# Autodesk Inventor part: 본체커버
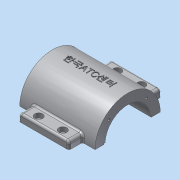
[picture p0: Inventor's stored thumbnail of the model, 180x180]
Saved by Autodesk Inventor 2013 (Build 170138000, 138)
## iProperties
Created: 2015-12
Part Number: 본체커버
Material: 알루미늄 6061
Document SubType Name: Modeling
Designer: mduedu
Density: 2.71 g/cm^3
Mass: 199.348 g
Surface Area: 200.806 cm^2
Volume: 73.5601 cm^3
Author: mduedu
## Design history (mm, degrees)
sketch "스케치1"
  geometry: L1 (45, 40)-(-45, 40); L2 (-45, 40)-(-45, -40); L3 (-45, -40)-(45, -40); L4 (45, -40)-(45, 40); L5 (45, 40)-(-45, -40); L6 (-45, 40)-(45, -40); 1 further point
  constraints: 12 end point, 2 midpoint, 2 parallel, 1 horizontal, 1 perpendicular
  dimensions: "d0" = 90 distance of L2.end L3.end; "d2" = 80 distance of L1.end L2.end
extrude "돌출1" new body sketch "스케치1" distance "d3" = 10; taper "d4" = 0 deg
sketch "스케치2"
  geometry: L1 (0, 40)-(0, -40) reference; C1 r 32.5 at (80, 0); 1 further point
  constraints: 1 centre point
  dimensions: "d5" = 65 diameter of C1; "d6" = 80 distance from line of C1.centre L1
extrude "돌출2" join sketch "스케치2" stored distance "d7" = 75; taper "d8" = 0 deg
sketch "스케치3"
  geometry: L1 (-27.5, -20)-(27.5, -20); L2 (27.5, -20)-(27.5, 20); L3 (27.5, 20)-(-27.5, 20); L4 (-27.5, 20)-(-27.5, -20); L5 (-27.5, -20)-(27.5, 20); L6 (27.5, -20)-(-27.5, 20); 1 further point
  constraints: 12 end point, 2 midpoint, 2 parallel, 1 horizontal, 1 perpendicular
  dimensions: "d9" = 55 distance of L2.end L3.end; "d11" = 40 distance of L1.end L2.end
extrude "돌출3" new body sketch "스케치3" stored distance "d12" = 75; taper "d13" = 0 deg
fillet "모깎기1"
fillet "모깎기2"
feature "결합1"
  node "솔리드2"
fillet "모깎기3" dims "d14" = 10
sketch "스케치4"
  geometry: L1 (-37.5, 47.5)-(37.5, 47.5) reference; L2 (35, 10)-(45, 10) reference; L3 (32.5, 47.5)-(40, 10); L4 (37.5, 47.5)-(37.5, 112.5) reference; L5 (45, 10)-(45, 0) reference; 1 further point
  constraints: 2 end point, 1 midpoint, 1 point on line
  dimensions: "d15" = 5 distance from line of L3.start L4; "d16" = 5 distance from line of L3.end L5
sketch "스케치5"
  geometry: L1 (10, 40)-(10, 30) reference; L2 (10, 35)-(56.569, 22.522); L3 (0, 40)-(10, 40) reference; 2 further points
  constraints: 2 end point, 1 midpoint, 2 other
  dimensions: "d17" = 5 distance from line of L2.start L3; "d18" = 15 deg angle of L2 L3
feature "리브1" dims "d19" = 1, "d20" = 6, "d21" = 0, "d22" = 0, "d23" = 1, "d24" = 1
feature "리브2" dims "d25" = 1, "d26" = 6, "d27" = 0, "d28" = 0, "d29" = 1, "d30" = 1
fillet "모깎기4" dims "d31" = 2
fillet "모깎기5" dims "d32" = 2
fillet "모깎기6" dims "d33" = 2
sketch "스케치6"
  geometry: A1 r 10 centre (-35, 30) between (-35, 40) and (-45, 30) reference; A2 r 10 centre (35, 30) between (45, 30) and (35, 40) reference; A3 r 10 centre (35, -30) between (35, -40) and (45, -30) reference; A4 r 10 centre (-35, -30) between (-45, -30) and (-35, -40) reference; 5 further points
  constraints: 4 coincident
hole "구멍1" sketch "스케치6" at (-35, 30), (35, 30), (35, -30), (-35, -30) diameter "d34" = 7; stored, may be unused: countersink angle "d38" = 90 deg, drill point angle "d40" = 118 deg; dims "d35" = 6, "d36" = 12, "d37" = 3, "d39" = 8
fillet "모깎기7" dims "d41" = 2
hole "구멍2" diameter "d44" = 45; stored, may be unused: countersink angle "d48" = 90 deg, drill point angle "d50" = 118 deg; dims "d42" = 10, "d43" = 10, "d45" = 6, "d46" = 4, "d47" = 2, "d49" = 8
sketch "스케치7" dims "d52" = 26.5
  geometry: L1 (0, 0)-(32.5, 0); L2 (0, 0)-(22.981, 22.981); A1 r 32.5 centre (0, 0) between (32.5, 0) and (22.981, 22.981) reference; 3 further points
  constraints: 4 end point, 2 point on circle, 1 coincident, 1 horizontal, 1 point on line, 3 other
  dimensions: "d51" = 45 deg angle of L2 L1
hole "구멍3" sketch "스케치7" at (18.738, 18.738) diameter "d54" = 2.459; stored, may be unused: countersink angle "d58" = 90 deg, drill point angle "d60" = 118 deg; dims "d55" = 8, "d56" = 4, "d57" = 2, "d59" = 10
sketch "스케치8"
  geometry: L1 (72.5, 31.623)-(72.5, 46); L2 (72.5, 46)-(87.5, 46); L3 (87.5, 46)-(87.5, 31.623); A1 r 32.5 centre (80, 0) between (87.5, 31.623) and (72.5, 31.623) reference; 2 further points
  constraints: 6 end point, 2 point on circle, 1 midpoint, 1 parallel, 1 vertical, 1 vertical alignment
  dimensions: "d64" = 15 distance of L1.end L2.end; "d66" = 46 distance from line of L2 A1.centre
extrude "돌출4" join sketch "스케치8" stored distance "d67" = 50; taper "d68" = 0 deg
fillet "모깎기8" dims "d69" = 3
fillet "모깎기9" dims "d70" = 2
sketch "스케치13"
  geometry: L1 (-46, 80)-(106, 80); L2 (106, 80)-(106, -30); L3 (106, -30)-(-46, -30); L4 (-46, -30)-(-46, 80); L5 (0, 0)-(60, 0) reference; L6 (76, 75.5)-(76, 84.5) reference; C1 r 32.5 at (30, 80) reference; 1 further point
  constraints: 8 end point, 2 parallel, 1 coincident, 1 horizontal, 1 midpoint, 1 perpendicular
  dimensions: "d99" = 30 distance between parallel lines of L3 L5; "d100" = 30 distance between parallel lines of L2 L6
extrude "돌출8" cut sketch "스케치13" stored distance "d97" = 10; taper "d98" = 0 deg
node "작업 평면2"
sketch "스케치14"
  geometry: 2 further points
  constraints: 1 coincident, 1 other
feature "엠보싱1" sketch "스케치14" dims "d28" = 0, "d102" = 0.5, "d103" = 0
feature "립1" dims "d104" = 1, "d105" = 1.1, "d106" = 0, "d107" = 0, "d108" = 3 deg, "d109" = 0
sketch "스케치15"
  geometry: L1 (-3, -1.039)-(-3, -10.834) reference; L2 (47, -10.834)-(47, -1.039) reference; L3 (-3, -5.936)-(47, -5.936); L4 (-15.5, 65.666)-(-15.5, 0.666) reference; L5 (59.5, 0.666)-(59.5, 65.666) reference; L6 (-15.5, 33.166)-(59.5, 33.166); 5 further points
  constraints: 4 end point, 4 midpoint, 2 point on line, 2 symmetric about line
  dimensions: "d110" = 13 distance from line of point (10, -5.936) L1; "d111" = 13 distance from line of point (34, -5.936) L2
sketch "스케치16"
  geometry: 4 further points
hole "구멍5" sketch "스케치16" at (34, -5.936), (10, 72.269), (34, 72.269), (10, -5.936) diameter "d112" = 4.5; stored, may be unused: countersink angle "d116" = 90 deg, drill point angle "d118" = 0 deg; dims "d113" = 6, "d114" = 8, "d115" = 4.6, "d117" = 8
node "솔리드1"
mirror "대칭1"
mirror "대칭2"
pattern_circular "원형 패턴1" dims angle "d62" = 360 deg
mirror "대칭3"
mirror "대칭4"
